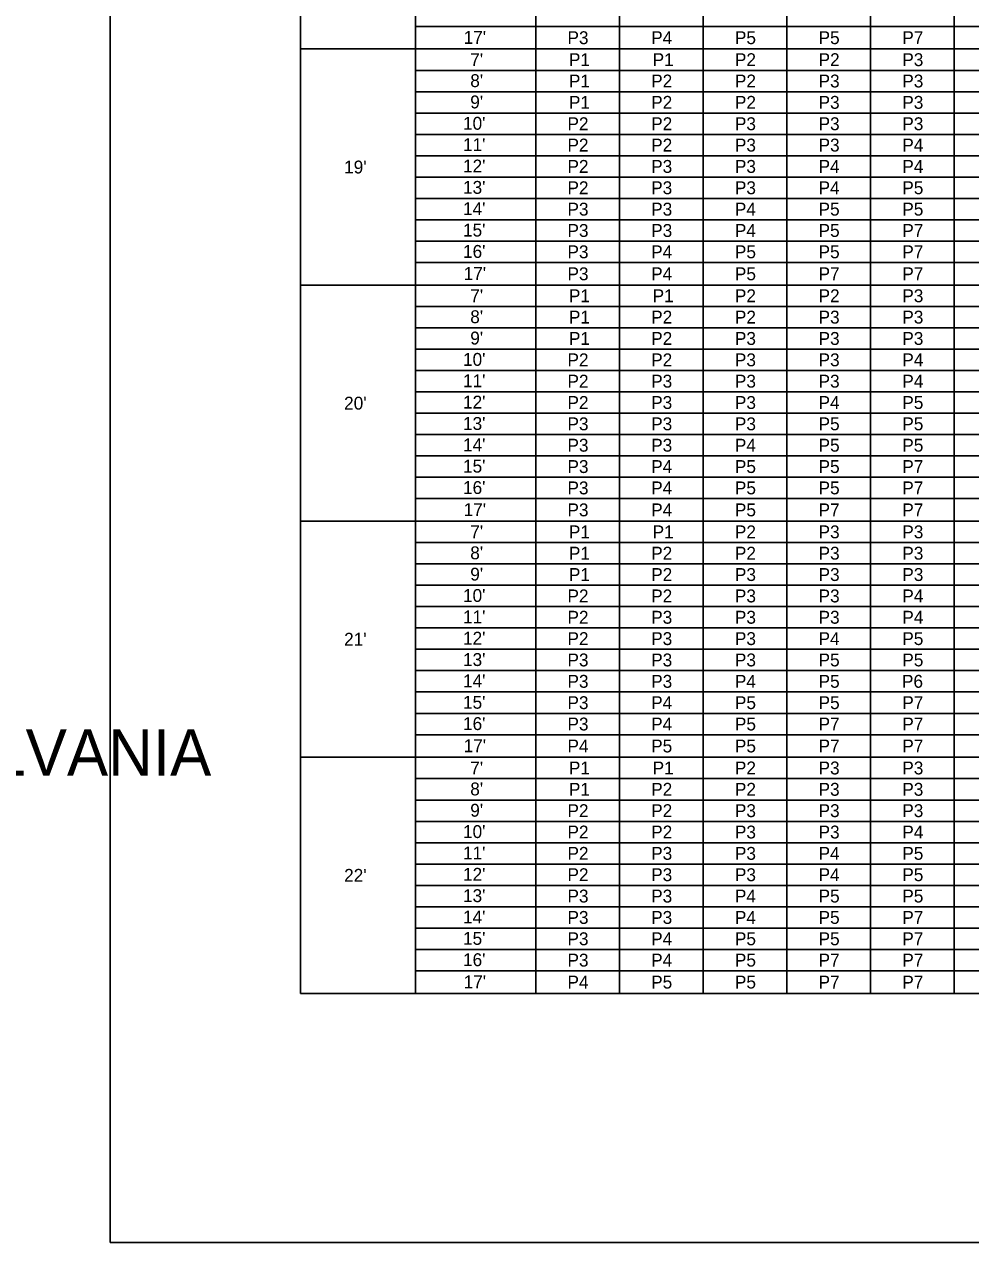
# Model space of a CAD drawing. Extents: x 637580 to 641008, y 294594 to 295782.
# Drawn here: x 639282.3 to 639502.8, y 295202.6 to 295486.4 of the extents above; entities that cross this region are included whole.
import ezdxf

# ---------------------------------------------------------------- set-up
doc = ezdxf.new("R2010")
doc.units = 0
doc.layers.add('1', color=7, linetype='Continuous')
doc.layers.add('2', color=7, linetype='Continuous')

msp = doc.modelspace()

# ---------------------------------------------------------------- linework, layer by layer
at = {"layer": '1'}
for p, q in [((639302.31, 295766.63), (639302.31, 295202.63)), ((639346.67, 295260.68), (639346.67, 295724.98)), ((639373.47, 295260.68), (639373.47, 295717.3)), ((639401.48, 295260.68), (639401.48, 295717.3)), ((639346.67, 295480.64), (639713.6, 295480.64)), ((639346.67, 295425.65), (639713.6, 295425.65)), ((639346.67, 295370.66), (639713.6, 295370.66)), ((639346.67, 295315.67), (639713.6, 295315.67)), ((639346.67, 295260.68), (639713.6, 295260.68)), ((640088.31, 295202.63), (639302.31, 295202.63)), ((639302.31, 295202.63), (639888.31, 295202.63))]:
    msp.add_line(p, q, dxfattribs=at)
at = {"layer": '2'}
for p, q in [((639401.48, 295260.68), (639401.48, 295717.3)), ((639420.98, 295260.68), (639420.98, 295709.96)), ((639440.49, 295260.68), (639440.49, 295709.96)), ((639460, 295260.68), (639460, 295709.96)), ((639479.51, 295260.68), (639479.51, 295709.96)), ((639499.01, 295260.68), (639499.01, 295709.96)), ((639373.47, 295485.9), (639713.6, 295485.9)), ((639373.47, 295475.66), (639713.6, 295475.66)), ((639373.47, 295470.69), (639713.6, 295470.69)), ((639373.47, 295465.72), (639713.6, 295465.72)), ((639373.47, 295460.75), (639713.6, 295460.75)), ((639373.47, 295455.77), (639713.6, 295455.77)), ((639373.47, 295450.8), (639713.6, 295450.8)), ((639373.47, 295445.83), (639713.6, 295445.83)), ((639373.47, 295440.86), (639713.6, 295440.86)), ((639373.47, 295435.88), (639713.6, 295435.88)), ((639373.47, 295430.91), (639713.6, 295430.91)), ((639373.47, 295420.67), (639713.6, 295420.67)), ((639373.47, 295415.7), (639713.6, 295415.7)), ((639373.47, 295410.73), (639713.6, 295410.73)), ((639373.47, 295405.76), (639713.6, 295405.76)), ((639373.47, 295400.78), (639713.6, 295400.78)), ((639373.47, 295395.81), (639713.6, 295395.81)), ((639373.47, 295390.84), (639713.6, 295390.84)), ((639373.47, 295385.87), (639713.6, 295385.87)), ((639373.47, 295380.89), (639713.6, 295380.89)), ((639373.47, 295375.92), (639713.6, 295375.92)), ((639373.47, 295365.68), (639713.6, 295365.68)), ((639373.47, 295360.71), (639713.6, 295360.71)), ((639373.47, 295355.74), (639713.6, 295355.74)), ((639373.47, 295350.77), (639713.6, 295350.77)), ((639373.47, 295345.79), (639713.6, 295345.79)), ((639373.47, 295340.82), (639713.6, 295340.82)), ((639373.47, 295335.85), (639713.6, 295335.85)), ((639373.47, 295330.88), (639713.6, 295330.88)), ((639373.47, 295325.9), (639713.6, 295325.9)), ((639373.47, 295320.93), (639713.6, 295320.93)), ((639373.47, 295310.69), (639713.6, 295310.69)), ((639373.47, 295305.72), (639713.6, 295305.72)), ((639373.47, 295300.75), (639713.6, 295300.75)), ((639373.47, 295295.78), (639713.6, 295295.78)), ((639373.47, 295290.8), (639713.6, 295290.8)), ((639373.47, 295285.83), (639713.6, 295285.83)), ((639373.47, 295280.86), (639713.6, 295280.86)), ((639373.47, 295275.89), (639713.6, 295275.89)), ((639373.47, 295270.91), (639713.6, 295270.91)), ((639373.47, 295265.94), (639713.6, 295265.94))]:
    msp.add_line(p, q, dxfattribs=at)

# ---------------------------------------------------------------- texts
at = {"layer": '1'}
for s, height, p in [("17'", 3, (639384.69, 295481.83)), ('P3', 3, (639408.88, 295481.77)), ('P4', 3, (639428.39, 295481.77)), ('P5', 3, (639447.9, 295481.77)), ('P5', 3, (639467.4, 295481.77)), ('P7', 3, (639486.91, 295481.77)), ("7'", 3, (639386.23, 295476.65)), ('P1', 3, (639409.22, 295476.65)), ('P1', 3, (639428.73, 295476.65)), ('P2', 3, (639447.9, 295476.65)), ('P2', 3, (639467.4, 295476.65)), ('P3', 3, (639486.91, 295476.65)), ("8'", 3, (639386.23, 295471.77)), ('P1', 3, (639409.22, 295471.68)), ('P2', 3, (639428.39, 295471.68)), ('P2', 3, (639447.9, 295471.68)), ('P3', 3, (639467.4, 295471.68)), ('P3', 3, (639486.91, 295471.68)), ("9'", 3, (639386.23, 295466.8)), ('P1', 3, (639409.22, 295466.71)), ('P2', 3, (639428.39, 295466.71)), ('P2', 3, (639447.9, 295466.71)), ('P3', 3, (639467.4, 295466.71)), ('P3', 3, (639486.91, 295466.71)), ("10'", 3, (639384.54, 295461.83)), ('P2', 3, (639408.88, 295461.73)), ('P2', 3, (639428.39, 295461.73)), ('P3', 3, (639447.9, 295461.73)), ('P3', 3, (639467.4, 295461.73)), ('P3', 3, (639486.91, 295461.73)), ("11'", 3, (639384.54, 295456.85)), ('P2', 3, (639408.88, 295456.76)), ('P2', 3, (639428.39, 295456.76)), ('P3', 3, (639447.9, 295456.76)), ('P3', 3, (639467.4, 295456.76)), ('P4', 3, (639486.91, 295456.76)), ("19'", 3, (639356.83, 295451.64)), ("12'", 3, (639384.54, 295451.88)), ('P2', 3, (639408.88, 295451.79)), ('P3', 3, (639428.39, 295451.79)), ('P3', 3, (639447.9, 295451.79)), ('P4', 3, (639467.4, 295451.79)), ('P4', 3, (639486.91, 295451.79)), ("13'", 3, (639384.54, 295446.91)), ('P2', 3, (639408.88, 295446.82)), ('P3', 3, (639428.39, 295446.82)), ('P3', 3, (639447.9, 295446.82)), ('P4', 3, (639467.4, 295446.82)), ('P5', 3, (639486.91, 295446.82)), ("14'", 3, (639384.54, 295441.94)), ('P3', 3, (639408.88, 295441.84)), ('P3', 3, (639428.39, 295441.84)), ('P4', 3, (639447.9, 295441.84)), ('P5', 3, (639467.4, 295441.84)), ('P5', 3, (639486.91, 295441.84)), ("15'", 3, (639384.54, 295436.96)), ('P3', 3, (639408.88, 295436.87)), ('P3', 3, (639428.39, 295436.87)), ('P4', 3, (639447.9, 295436.87)), ('P5', 3, (639467.4, 295436.87)), ('P7', 3, (639486.91, 295436.87)), ("16'", 3, (639384.54, 295431.99)), ('P3', 3, (639408.88, 295431.9)), ('P4', 3, (639428.39, 295431.9)), ('P5', 3, (639447.9, 295431.9)), ('P5', 3, (639467.4, 295431.9)), ('P7', 3, (639486.91, 295431.9)), ("17'", 3, (639384.69, 295426.84)), ('P3', 3, (639408.88, 295426.78)), ('P4', 3, (639428.39, 295426.78)), ('P5', 3, (639447.9, 295426.78)), ('P7', 3, (639467.4, 295426.78)), ('P7', 3, (639486.91, 295426.78)), ("7'", 3, (639386.23, 295421.66)), ('P1', 3, (639409.22, 295421.66)), ('P1', 3, (639428.73, 295421.66)), ('P2', 3, (639447.9, 295421.66)), ('P2', 3, (639467.4, 295421.66)), ('P3', 3, (639486.91, 295421.66)), ("8'", 3, (639386.23, 295416.78)), ('P1', 3, (639409.22, 295416.69)), ('P2', 3, (639428.39, 295416.69)), ('P2', 3, (639447.9, 295416.69)), ('P3', 3, (639467.4, 295416.69)), ('P3', 3, (639486.91, 295416.69)), ("9'", 3, (639386.23, 295411.81)), ('P1', 3, (639409.22, 295411.72)), ('P2', 3, (639428.39, 295411.72)), ('P3', 3, (639447.9, 295411.72)), ('P3', 3, (639467.4, 295411.72)), ('P3', 3, (639486.91, 295411.72)), ("10'", 3, (639384.54, 295406.84)), ('P2', 3, (639408.88, 295406.74)), ('P2', 3, (639428.39, 295406.74)), ('P3', 3, (639447.9, 295406.74)), ('P3', 3, (639467.4, 295406.74)), ('P4', 3, (639486.91, 295406.74)), ("11'", 3, (639384.54, 295401.86)), ('P2', 3, (639408.88, 295401.77)), ('P3', 3, (639428.39, 295401.77)), ('P3', 3, (639447.9, 295401.77)), ('P3', 3, (639467.4, 295401.77)), ('P4', 3, (639486.91, 295401.77)), ("20'", 3, (639356.83, 295396.65)), ("12'", 3, (639384.54, 295396.89)), ('P2', 3, (639408.88, 295396.8)), ('P3', 3, (639428.39, 295396.8)), ('P3', 3, (639447.9, 295396.8)), ('P4', 3, (639467.4, 295396.8)), ('P5', 3, (639486.91, 295396.8)), ("13'", 3, (639384.54, 295391.92)), ('P3', 3, (639408.88, 295391.83)), ('P3', 3, (639428.39, 295391.83)), ('P3', 3, (639447.9, 295391.83)), ('P5', 3, (639467.4, 295391.83)), ('P5', 3, (639486.91, 295391.83)), ("14'", 3, (639384.54, 295386.95)), ('P3', 3, (639408.88, 295386.85)), ('P3', 3, (639428.39, 295386.85)), ('P4', 3, (639447.9, 295386.85)), ('P5', 3, (639467.4, 295386.85)), ('P5', 3, (639486.91, 295386.85)), ("15'", 3, (639384.54, 295381.97)), ('P3', 3, (639408.88, 295381.88)), ('P4', 3, (639428.39, 295381.88)), ('P5', 3, (639447.9, 295381.88)), ('P5', 3, (639467.4, 295381.88)), ('P7', 3, (639486.91, 295381.88)), ("16'", 3, (639384.54, 295377)), ('P3', 3, (639408.88, 295376.91)), ('P4', 3, (639428.39, 295376.91)), ('P5', 3, (639447.9, 295376.91)), ('P5', 3, (639467.4, 295376.91)), ('P7', 3, (639486.91, 295376.91)), ("17'", 3, (639384.69, 295371.85)), ('P3', 3, (639408.88, 295371.79)), ('P4', 3, (639428.39, 295371.79)), ('P5', 3, (639447.9, 295371.79)), ('P7', 3, (639467.4, 295371.79)), ('P7', 3, (639486.91, 295371.79)), ("7'", 3, (639386.23, 295366.67)), ('P1', 3, (639409.22, 295366.67)), ('P1', 3, (639428.73, 295366.67)), ('P2', 3, (639447.9, 295366.67)), ('P3', 3, (639467.4, 295366.67)), ('P3', 3, (639486.91, 295366.67)), ("8'", 3, (639386.23, 295361.79)), ('P1', 3, (639409.22, 295361.7)), ('P2', 3, (639428.39, 295361.7)), ('P2', 3, (639447.9, 295361.7)), ('P3', 3, (639467.4, 295361.7)), ('P3', 3, (639486.91, 295361.7)), ("9'", 3, (639386.23, 295356.82)), ('P1', 3, (639409.22, 295356.73)), ('P2', 3, (639428.39, 295356.73)), ('P3', 3, (639447.9, 295356.73)), ('P3', 3, (639467.4, 295356.73)), ('P3', 3, (639486.91, 295356.73)), ("10'", 3, (639384.54, 295351.85)), ('P2', 3, (639408.88, 295351.75)), ('P2', 3, (639428.39, 295351.75)), ('P3', 3, (639447.9, 295351.75)), ('P3', 3, (639467.4, 295351.75)), ('P4', 3, (639486.91, 295351.75)), ("11'", 3, (639384.54, 295346.87)), ('P2', 3, (639408.88, 295346.78)), ('P3', 3, (639428.39, 295346.78)), ('P3', 3, (639447.9, 295346.78)), ('P3', 3, (639467.4, 295346.78)), ('P4', 3, (639486.91, 295346.78)), ("21'", 3, (639356.83, 295341.66)), ("12'", 3, (639384.54, 295341.9)), ('P2', 3, (639408.88, 295341.81)), ('P3', 3, (639428.39, 295341.81)), ('P3', 3, (639447.9, 295341.81)), ('P4', 3, (639467.4, 295341.81)), ('P5', 3, (639486.91, 295341.81)), ("13'", 3, (639384.54, 295336.93)), ('P3', 3, (639408.88, 295336.84)), ('P3', 3, (639428.39, 295336.84)), ('P3', 3, (639447.9, 295336.84)), ('P5', 3, (639467.4, 295336.84)), ('P5', 3, (639486.91, 295336.84)), ("14'", 3, (639384.54, 295331.96)), ('P3', 3, (639408.88, 295331.86)), ('P3', 3, (639428.39, 295331.86)), ('P4', 3, (639447.9, 295331.86)), ('P5', 3, (639467.4, 295331.86)), ('P6', 3, (639486.83, 295331.86)), ("15'", 3, (639384.54, 295326.98)), ('P3', 3, (639408.88, 295326.89)), ('P4', 3, (639428.39, 295326.89)), ('P5', 3, (639447.9, 295326.89)), ('P5', 3, (639467.4, 295326.89)), ('P7', 3, (639486.91, 295326.89)), ("16'", 3, (639384.54, 295322.01)), ('P3', 3, (639408.88, 295321.92)), ('P4', 3, (639428.39, 295321.92)), ('P5', 3, (639447.9, 295321.92)), ('P7', 3, (639467.4, 295321.92)), ('P7', 3, (639486.91, 295321.92)), ('COMMONWEALTH OF PENNSYLVANIA', 10.7828, (639059.9, 295311.36)), ("17'", 3, (639384.69, 295316.86)), ('P4', 3, (639408.88, 295316.8)), ('P5', 3, (639428.39, 295316.8)), ('P5', 3, (639447.9, 295316.8)), ('P7', 3, (639467.4, 295316.8)), ('P7', 3, (639486.91, 295316.8)), ("7'", 3, (639386.23, 295311.68)), ('P1', 3, (639409.22, 295311.68)), ('P1', 3, (639428.73, 295311.68)), ('P2', 3, (639447.9, 295311.68)), ('P3', 3, (639467.4, 295311.68)), ('P3', 3, (639486.91, 295311.68)), ("8'", 3, (639386.23, 295306.8)), ('P1', 3, (639409.22, 295306.71)), ('P2', 3, (639428.39, 295306.71)), ('P2', 3, (639447.9, 295306.71)), ('P3', 3, (639467.4, 295306.71)), ('P3', 3, (639486.91, 295306.71)), ("9'", 3, (639386.23, 295301.83)), ('P2', 3, (639408.88, 295301.74)), ('P2', 3, (639428.39, 295301.74)), ('P3', 3, (639447.9, 295301.74)), ('P3', 3, (639467.4, 295301.74)), ('P3', 3, (639486.91, 295301.74)), ("10'", 3, (639384.54, 295296.86)), ('P2', 3, (639408.88, 295296.76)), ('P2', 3, (639428.39, 295296.76)), ('P3', 3, (639447.9, 295296.76)), ('P3', 3, (639467.4, 295296.76)), ('P4', 3, (639486.91, 295296.76)), ("11'", 3, (639384.54, 295291.88)), ('P2', 3, (639408.88, 295291.79)), ('P3', 3, (639428.39, 295291.79)), ('P3', 3, (639447.9, 295291.79)), ('P4', 3, (639467.4, 295291.79)), ('P5', 3, (639486.91, 295291.79)), ("22'", 3, (639356.83, 295286.67)), ("12'", 3, (639384.54, 295286.91)), ('P2', 3, (639408.88, 295286.82)), ('P3', 3, (639428.39, 295286.82)), ('P3', 3, (639447.9, 295286.82)), ('P4', 3, (639467.4, 295286.82)), ('P5', 3, (639486.91, 295286.82)), ("13'", 3, (639384.54, 295281.94)), ('P3', 3, (639408.88, 295281.85)), ('P3', 3, (639428.39, 295281.85)), ('P4', 3, (639447.9, 295281.85)), ('P5', 3, (639467.4, 295281.85)), ('P5', 3, (639486.91, 295281.85)), ("14'", 3, (639384.54, 295276.97)), ('P3', 3, (639408.88, 295276.87)), ('P3', 3, (639428.39, 295276.87)), ('P4', 3, (639447.9, 295276.87)), ('P5', 3, (639467.4, 295276.87)), ('P7', 3, (639486.91, 295276.87)), ("15'", 3, (639384.54, 295271.99)), ('P3', 3, (639408.88, 295271.9)), ('P4', 3, (639428.39, 295271.9)), ('P5', 3, (639447.9, 295271.9)), ('P5', 3, (639467.4, 295271.9)), ('P7', 3, (639486.91, 295271.9)), ("16'", 3, (639384.54, 295267.02)), ('P3', 3, (639408.88, 295266.93)), ('P4', 3, (639428.39, 295266.93)), ('P5', 3, (639447.9, 295266.93)), ('P7', 3, (639467.4, 295266.93)), ('P7', 3, (639486.91, 295266.93)), ("17'", 3, (639384.69, 295261.87)), ('P4', 3, (639408.88, 295261.81)), ('P5', 3, (639428.39, 295261.81)), ('P5', 3, (639447.9, 295261.81)), ('P7', 3, (639467.4, 295261.81)), ('P7', 3, (639486.91, 295261.81))]:
    msp.add_text(s, height=height, dxfattribs=at).set_placement(p)

doc.saveas('drawing.dxf')
